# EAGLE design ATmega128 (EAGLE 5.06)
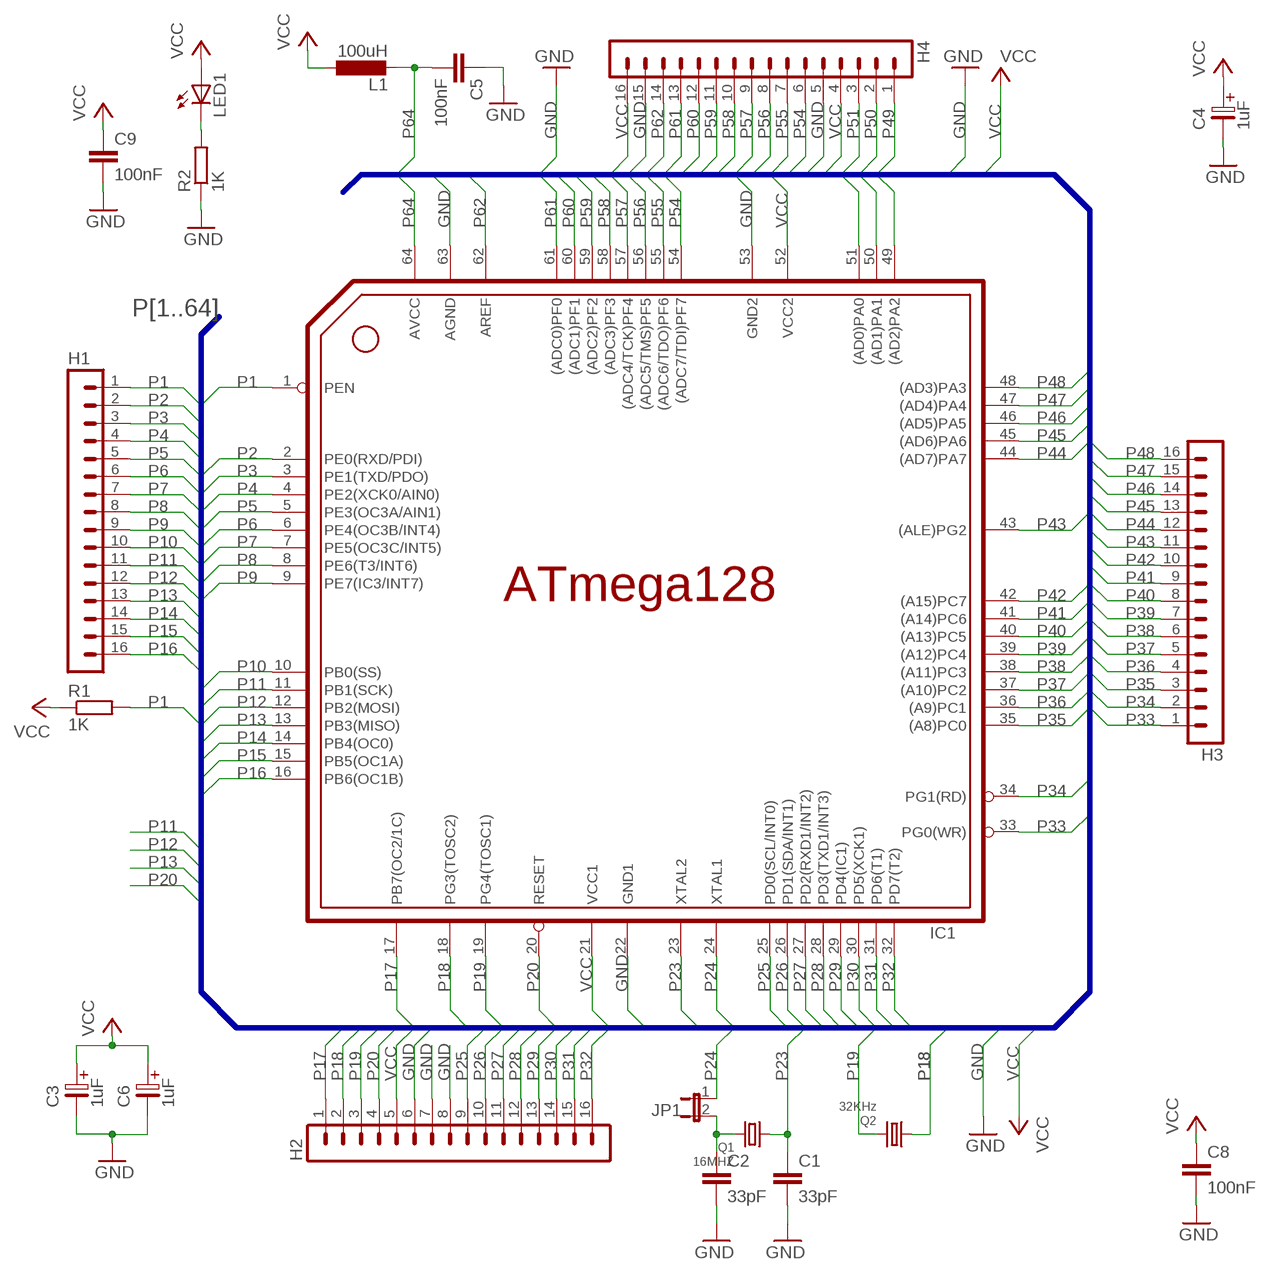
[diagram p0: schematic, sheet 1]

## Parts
C1  33pF  CAP2.5  [CAP2.5]
C2  33pF  CAP2.5  [CAP2.5]
C3  1uF  ELC2.5  [ELC2.5]
C4  1uF  ELC2.5  [ELC2.5]
C5  100nF  CAP2.5  [CAP2.5]
C6  1uF  ELC2.5  [ELC2.5]
C8  100nF  CAP2.5  [CAP2.5]
C9  100nF  CAP2.5  [CAP2.5]
H1  HEADER-16PIN  [HEADER-16PIN]
H2  HEADER-16PIN  [HEADER-16PIN]
H3  HEADER-16PIN  [HEADER-16PIN]
H4  HEADER-16PIN  [HEADER-16PIN]
IC1  ATMEGA128TQFP  [HEADER64PIN_MCU]
JP1  JP1E  [JP1]
L1  100uH  L-EU0204/7  [0204/7]
LED1  LED3MM  [LED3MM]
Q1  16MHZ  CRYSTALHC  [HC49]
Q2  32KHz  CRYSTALTC  [TC26]
R1  1K  R-5-7M  [R-7]
R2  1K  R-5-7M  [R-7]

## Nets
GND: C1.2 C2.2 C3.2 C4.2 C5.1 C6.2 C8.2 C9.2 H2.6 H2.7 H2.8 H4.5 H4.15 IC1.22(GND1) IC1.53(GND2) IC1.63(AGND) R2.1
N$1: LED1.K(C) R2.2
N$66: C2.1 JP1.2 Q1.2
P1: H1.1 IC1.1(PEN) R1.2
P2: H1.2 IC1.2(PE0(RXD/PDI))
P3: H1.3 IC1.3(PE1(TXD/PDO))
P4: H1.4 IC1.4(PE2(XCK0/AIN0))
P5: H1.5 IC1.5(PE3(OC3A/AIN1))
P6: H1.6 IC1.6(PE4(OC3B/INT4))
P7: H1.7 IC1.7(PE5(OC3C/INT5))
P8: H1.8 IC1.8(PE6(T3/INT6))
P9: H1.9 IC1.9(PE7(IC3/INT7))
P10: H1.10 IC1.10(PB0(SS))
P11: H1.11 IC1.11(PB1(SCK))
P12: H1.12 IC1.12(PB2(MOSI))
P13: H1.13 IC1.13(PB3(MISO))
P14: H1.14 IC1.14(PB4(OC0))
P15: H1.15 IC1.15(PB5(OC1A))
P16: H1.16 IC1.16(PB6(OC1B))
P17: H2.1 IC1.17(PB7(OC2/1C))
P18: H2.2 IC1.18(PG3(TOSC2)) Q2.1
P19: H2.3 IC1.19(PG4(TOSC1)) Q2.2
P20: H2.4 IC1.20(RESET)
P23: C1.1 IC1.23(XTAL2) Q1.1
P24: IC1.24(XTAL1) JP1.1
P25: H2.9 IC1.25(PD0(SCL/INT0))
P26: H2.10 IC1.26(PD1(SDA/INT1))
P27: H2.11 IC1.27(PD2(RXD1/INT2))
P28: H2.12 IC1.28(PD3(TXD1/INT3))
P29: H2.13 IC1.29(PD4(IC1))
P30: H2.14 IC1.30(PD5(XCK1))
P31: H2.15 IC1.31(PD6(T1))
P32: H2.16 IC1.32(PD7(T2))
P33: H3.1 IC1.33(PG0(WR))
P34: H3.2 IC1.34(PG1(RD))
P35: H3.3 IC1.35((A8)PC0)
P36: H3.4 IC1.36((A9)PC1)
P37: H3.5 IC1.37((A10)PC2)
P38: H3.6 IC1.38((A11)PC3)
P39: H3.7 IC1.39((A12)PC4)
P40: H3.8 IC1.40((A13)PC5)
P41: H3.9 IC1.41((A14)PC6)
P42: H3.10 IC1.42((A15)PC7)
P43: H3.11 IC1.43((ALE)PG2)
P44: H3.12 IC1.44((AD7)PA7)
P45: H3.13 IC1.45((AD6)PA6)
P46: H3.14 IC1.46((AD5)PA5)
P47: H3.15 IC1.47((AD4)PA4)
P48: H3.16 IC1.48((AD3)PA3)
P49: H4.1 IC1.49((AD2)PA2)
P50: H4.2 IC1.50((AD1)PA1)
P51: H4.3 IC1.51((AD0)PA0)
P54: H4.6 IC1.54((ADC7/TDI)PF7)
P55: H4.7 IC1.55((ADC6/TDO)PF6)
P56: H4.8 IC1.56((ADC5/TMS)PF5)
P57: H4.9 IC1.57((ADC4/TCK)PF4)
P58: H4.10 IC1.58((ADC3)PF3)
P59: H4.11 IC1.59((ADC2)PF2)
P60: H4.12 IC1.60((ADC1)PF1)
P61: H4.13 IC1.61((ADC0)PF0)
P62: H4.14 IC1.62(AREF)
P64: C5.2 IC1.64(AVCC) L1.2
VCC: C3.1 C4.1 C6.1 C8.1 C9.1 H2.5 H4.4 H4.16 IC1.21(VCC1) IC1.52(VCC2) L1.1 LED1.A R1.1

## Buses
P[1..64]

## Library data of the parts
C1 C2 C5 C8 C9 = WALID2008A:CAP: Ceramic Capacitor
C3 C4 C6 = WALID2008A:ELC: Electric Capacitor
H1-H4 = WALID2008A:HEADER-16PIN: Header 16 Pin
IC1 = WALID2008A:ATMEGA128: MICROCONTROLLER 128 Kbytes FLASH 4 Kbytes SRAM 4 Kbytes EEPROM DUAL USART 8-channel 10 bit ADC
JP1 = jumper:JP1E: JUMPER
L1 = WALID2008A:L-EU: INDUCTOR, European symbol
LED1 = led:LED: LED
Q1 Q2 = WALID2008A:CRYSTAL: Crystal
R1 R2 = WALID2008A:R-5: Resistor 5, 7,8, 10, 12, 13, 15, 17, 19, 20, 25, 28, 30mm

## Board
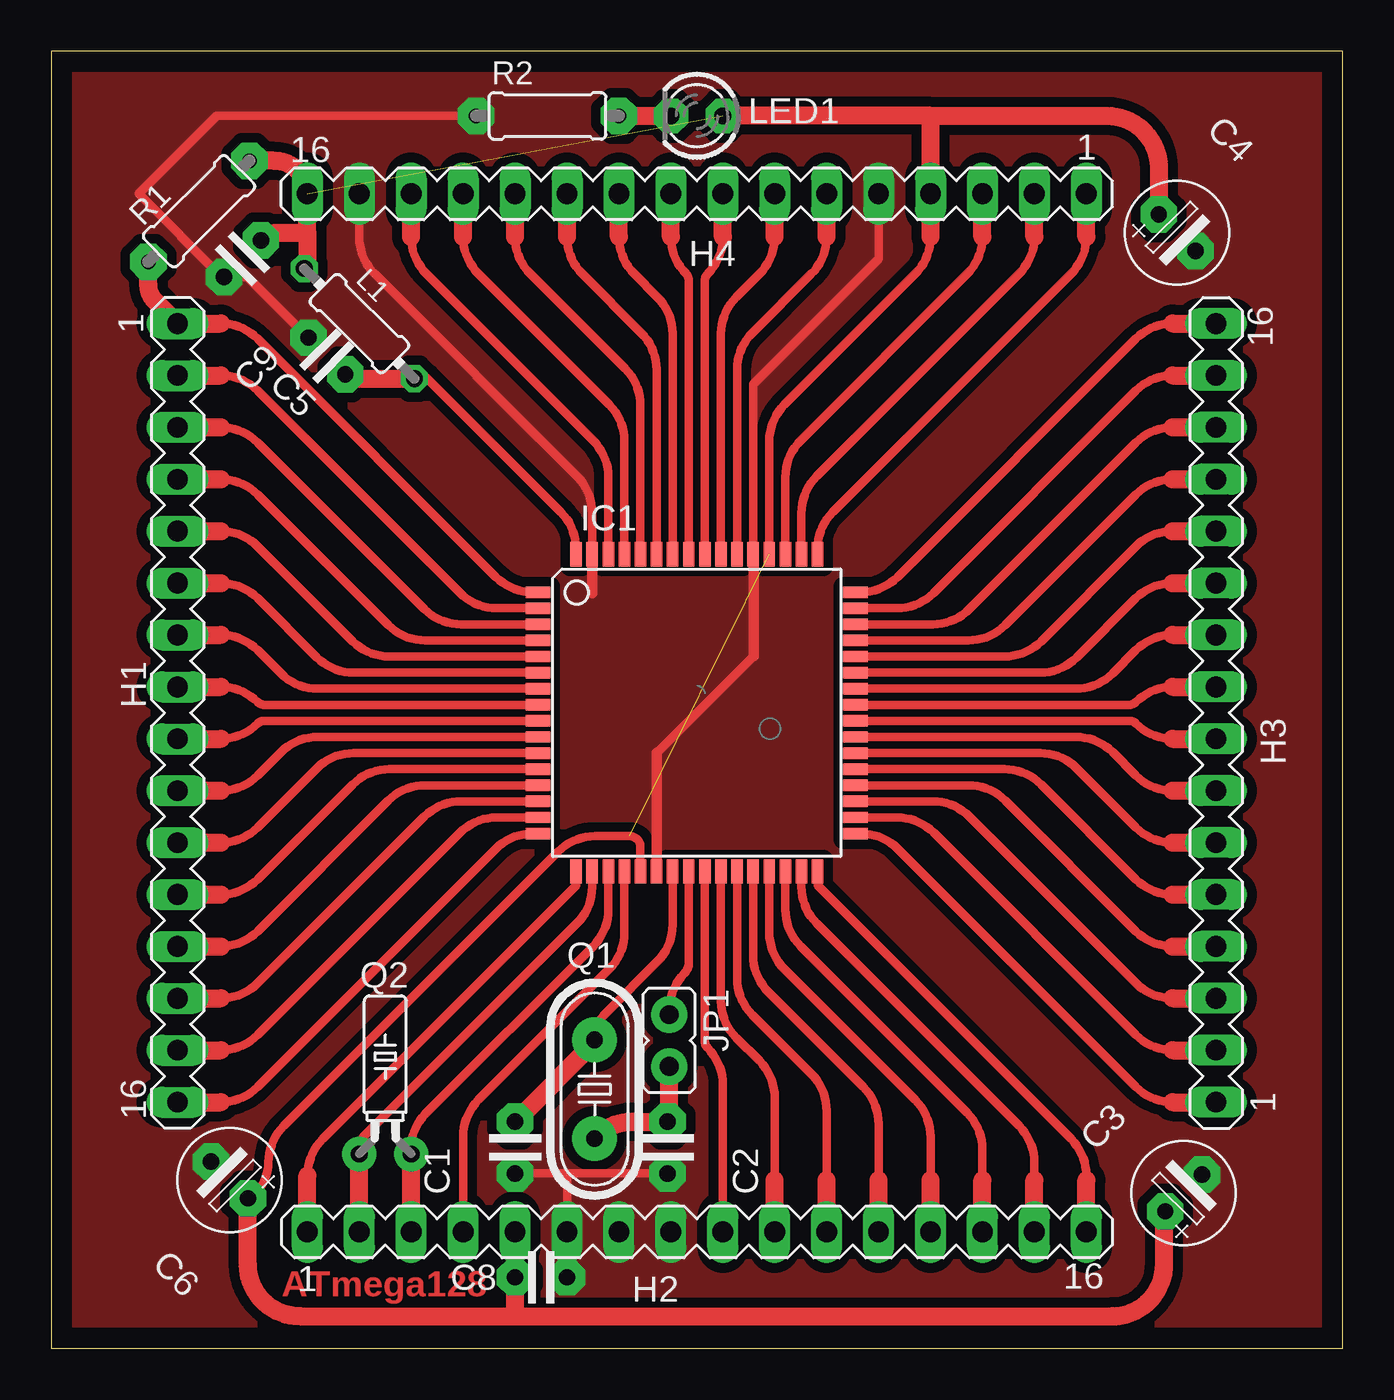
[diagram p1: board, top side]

Size 63.17 x 63.48 mm. Coordinates in mm from the lower left corner, seen from the top.
Outline: 0,63.48 0,0 63.17,0 63.17,63.48 0,63.48
Copper layers (1*16): Top 0.035mm / dielectric 1.5mm / Bottom 0.035mm
Design rules "default *": minimum track width 20mil, minimum drill 24mil, track to track 8mil, track to pad 8mil, pad to pad 8mil, via to via 8mil, smd to smd 8mil, copper to edge 40mil, drill to drill 8mil, minimum pad ring 10mil, minimum via ring 8mil, stop-mask expansion 4mil, vias tented up to drill 0mil, thermal gap 10mil

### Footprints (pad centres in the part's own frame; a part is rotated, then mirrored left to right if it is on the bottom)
CAP2.5 = drill 0.8 pad 1.778 octagon: 1 -1.27,0; 2 1.27,0
ELC2.5 = drill 0.8 pad 1.778 octagon: 1 -1.27,0; 2 1.27,0
HEADER-16PIN = drill 1.016 long: 1 -17.78,0; 2 -15.24,0; 3 -12.7,0; 4 -10.16,0; 5 -7.62,0; 6 -5.08,0; 7 -2.54,0; 8 0,0; 9 2.54,0; 10 5.08,0; 11 7.62,0; 12 10.16,0; 13 12.7,0; 14 15.24,0; 15 17.78,0; 16 20.32,0
HEADER64PIN_MCU = smd 1.194 x 0.559: 1 -7.76,5.905; 2 -7.76,5.118; 3 -7.76,4.331; 4 -7.76,3.543; 5 -7.76,2.756; 6 -7.76,1.968; 7 -7.76,1.181; 8 -7.76,0.394; 9 -7.76,-0.394; 10 -7.76,-1.181; 11 -7.76,-1.968; 12 -7.76,-2.756; 13 -7.76,-3.543; 14 -7.76,-4.331; 15 -7.76,-5.118; 16 -7.76,-5.905; 33 7.76,-5.905; 34 7.76,-5.118; 35 7.76,-4.331; 36 7.76,-3.543; 37 7.76,-2.756; 38 7.76,-1.968; 39 7.76,-1.181; 40 7.76,-0.394; 41 7.76,0.394; 42 7.76,1.181; 43 7.76,1.968; 44 7.76,2.756; 45 7.76,3.543; 46 7.76,4.331; 47 7.76,5.118; 48 7.76,5.905 | smd 0.559 x 1.194: 17 -5.905,-7.76; 18 -5.118,-7.76; 19 -4.331,-7.76; 20 -3.543,-7.76; 21 -2.756,-7.76; 22 -1.968,-7.76; 23 -1.181,-7.76; 24 -0.394,-7.76; 25 0.394,-7.76; 26 1.181,-7.76; 27 1.968,-7.76; 28 2.756,-7.76; 29 3.543,-7.76; 30 4.331,-7.76; 31 5.118,-7.76; 32 5.905,-7.76; 49 5.905,7.76; 50 5.118,7.76; 51 4.331,7.76; 52 3.543,7.76; 53 2.756,7.76; 54 1.968,7.76; 55 1.181,7.76; 56 0.394,7.76; 57 -0.394,7.76; 58 -1.181,7.76; 59 -1.968,7.76; 60 -2.756,7.76; 61 -3.543,7.76; 62 -4.331,7.76; 63 -5.118,7.76; 64 -5.905,7.76
JP1 = drill 0.914 pad 1.778 round: 1 0,-1.27; 2 0,1.27
0204/7 = drill 0.813 octagon: 1 -3.81,0; 2 3.81,0
LED3MM = drill 0.813 pad 1.676 octagon: A -1.27,0; K 1.27,0
HC49 = drill 0.813 pad 2.184 round: 1 -2.413,0; 2 2.413,0
TC26 = drill 0.813 pad 1.676 round: 1 -1.27,-5.08; 2 1.27,-5.08
R-7 = drill 0.7 pad 1.778 octagon: 1 -3.175,0; 2 3.81,0

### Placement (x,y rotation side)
C1  22.69,9.83 270 top
C2  30.16,9.83 270 top
C3  55.4,7.6 45 top
C4  55.08,54.59 315 top
C5  13.49,48.56 315 top
C6  8.72,8.24 135 top
C8  23.97,3.48 0 top
C9  9.36,53.33 225 top
H1  6.19,32.37 270 top
H2  30.31,5.7 0 top
H3  56.98,29.83 90 top
H4  32.86,56.5 180 top
IC1  31.58,31.1 0 top
JP1  30.24,15.07 180 top
L1  15.08,50.15 315 top
LED1  31.58,60.31 180 top
Q1  26.58,12.69 270 top
Q2  16.34,14.59 0 top
R1  7.45,55.86 225 top
R2  23.97,60.31 0 top

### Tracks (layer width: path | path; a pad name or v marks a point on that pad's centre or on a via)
GND
  Top 0.406: H4.5 40.47,53.33 34.34,47.19 IC1.53 34.34,38.74 34.36,38.72 | C1.2 25.23,8.56 | 25.23,8.56 C2.2 30.31,8.56 | 25.23,8.56 H2.6 | 29.62,29.13 34.36,33.88 | C5.1 9.62,52.43 C9.2 8.35,52.43 4.28,56.5 8.09,60.31 R2.1 | IC1.63 26.47,38.98 26.47,40.88 arc45 25.72,42.68 15.82,52.58 arc-45 15.08,54.38 H4.15
  Top 0.508: IC1.22 29.62,29.13 | 34.36,33.88 34.36,38.72 | 26.47,36.95 26.47,38.98
  pour Top (isolate 0.483, no thermals): -0.8,66.34 68.41,66.34 68.41,-0.97 -0.8,-0.97
N$1
  Top 0.889: R2.2 LED1.K
N$66
  Top 0.406: JP1.2 30.19,13.75 30.24,13.7 | C2.1 30.24,11.1
  Top 0.889: 30.24,11.1 30.24,13.7 | Q1.2 26.58,10.3 26.63,10.35 arc-45 28.43,11.1 C2.1
P1
  Top 0.406: 8.31,50.15 arc-45 10.1,49.41 21.76,37.75 arc45 23.56,37.01 IC1.1 | R1.2
  Top 0.889: 8.31,50.15 H1.1 5.08,51.25 arc-45 4.76,52.04 R1.2
P2
  Top 0.406: 8.31,47.61 arc-45 10.1,46.87 20.01,36.96 arc45 21.8,36.22 IC1.2
  Top 0.889: H1.2 8.31,47.61
P3
  Top 0.406: 8.31,45.07 arc-45 10.1,44.33 18.25,36.17 arc45 20.05,35.43 IC1.3
  Top 0.889: H1.3 8.31,45.07
P4
  Top 0.406: 8.31,42.53 arc-45 10.1,41.79 16.5,35.39 arc45 18.3,34.64 IC1.4
  Top 0.889: H1.4 8.31,42.53
P5
  Top 0.406: 8.31,39.99 arc-45 10.1,39.25 14.75,34.6 arc45 16.55,33.86 IC1.5
  Top 0.889: H1.5 8.31,39.99
P6
  Top 0.406: 8.31,37.45 arc-45 10.1,36.71 13,33.81 arc45 14.79,33.07 IC1.6
  Top 0.889: H1.6 8.31,37.45
P7
  Top 0.406: 8.31,34.91 arc-45 10.1,34.17 11.25,33.02 arc45 13.04,32.28 IC1.7
  Top 0.889: H1.7 8.31,34.91
P8
  Top 0.406: 8.31,32.37 arc-45 10.1,31.63 arc45 10.42,31.49 IC1.8
  Top 0.889: H1.8 8.31,32.37
P9
  Top 0.406: 8.31,29.83 arc45 10.1,30.57 arc-45 10.42,30.71 IC1.9
  Top 0.889: H1.9 8.31,29.83
P10
  Top 0.406: 8.31,27.29 arc45 10.1,28.03 11.25,29.17 arc-45 13.04,29.92 IC1.10
  Top 0.889: H1.10 8.31,27.29
P11
  Top 0.406: 8.31,24.75 arc45 10.1,25.49 13,28.39 arc-45 14.79,29.13 IC1.11
  Top 0.889: H1.11 8.31,24.75
P12
  Top 0.406: 8.31,22.21 arc45 10.1,22.95 14.75,27.6 arc-45 16.55,28.34 IC1.12
  Top 0.889: H1.12 8.31,22.21
P13
  Top 0.406: 8.31,19.67 arc45 10.1,20.41 16.5,26.81 arc-45 18.3,27.56 IC1.13
  Top 0.889: H1.13 8.31,19.67
P14
  Top 0.406: 8.31,17.13 arc45 10.1,17.87 18.25,26.02 arc-45 20.05,26.77 IC1.14
  Top 0.889: H1.14 8.31,17.13
P15
  Top 0.406: 8.31,14.59 arc45 10.1,15.33 20.01,25.24 arc-45 21.8,25.98 IC1.15
  Top 0.889: H1.15 8.31,14.59
P16
  Top 0.406: 8.31,12.05 arc45 10.1,12.79 21.76,24.45 arc-45 23.56,25.2 IC1.16
  Top 0.889: H1.16 8.31,12.05
P17
  Top 0.406: IC1.17 25.68,22.66 13.28,10.25 arc45 12.53,8.46
  Top 0.889: H2.1 12.53,8.46
P18
  Top 0.406: IC1.18 26.47,22.59 arc-45 25.72,20.79 15.3,10.37 arc45 15.08,9.83
  Top 0.889: H2.2 Q2.1
  Top 1.016: Q2.1 15.08,9.83
P19
  Top 0.406: 17.61,9.83 arc-45 18.29,11.45 26.51,19.67 arc45 27.25,21.47 IC1.19
  Top 0.889: H2.3 Q2.2
  Top 1.016: Q2.2 17.61,9.83
P20
  Top 0.406: H2.4 20.16,10.36 arc-45 20.9,12.16 27.3,18.56 arc45 28.04,20.35 IC1.20
P23
  Top 0.406: Q1.1 26.58,15.07 | Q1.1 | IC1.23 30.4,20.73 arc-45 29.66,18.94 27.12,16.4 arc45 Q1.1 | 26.58,14.99 Q1.1
  Top 0.889: C1.1 26.58,14.99
P24
  Top 0.406: JP1.1 30.24,16.55 arc-45 30.98,18.35 arc45 31.19,18.86 IC1.24
P25
  Top 0.406: H2.9 32.86,12.9 arc45 32.11,14.7 arc-45 31.98,15.02 IC1.25
P26
  Top 0.406: 35.39,8.24 35.39,12.27 arc45 34.65,14.06 33.51,15.21 arc-45 32.77,17 IC1.26
  Top 0.889: H2.10 35.39,8.24
P27
  Top 0.406: 37.94,8.24 37.94,11.63 arc45 37.19,13.43 34.3,16.32 arc-45 33.55,18.12 IC1.27
  Top 0.889: H2.11 37.94,8.24
P28
  Top 0.406: 40.47,8.24 40.47,11 arc45 39.73,12.79 35.08,17.44 arc-45 34.34,19.24 IC1.28
  Top 0.889: H2.12 40.47,8.24
P29
  Top 0.406: 43.02,8.24 43.02,10.36 arc45 42.27,12.16 35.87,18.56 arc-45 35.13,20.35 IC1.29
  Top 0.889: H2.13 43.02,8.24
P30
  Top 0.406: 45.55,8.24 45.55,9.73 arc45 44.81,11.52 36.66,19.67 arc-45 35.92,21.47 IC1.30
  Top 0.889: H2.14 45.55,8.24
P31
  Top 0.406: 48.09,8.24 48.09,9.09 arc45 47.35,10.89 37.45,20.79 arc-45 36.7,22.59 IC1.31
  Top 0.889: H2.15 48.09,8.24
P32
  Top 0.406: IC1.32 37.49,22.66 49.89,10.25 arc-45 50.63,8.46 50.63,8.24
  Top 0.889: H2.16 50.63,8.24
P33
  Top 0.406: IC1.33 39.61,25.2 arc-45 41.41,24.45 53.07,12.79 arc45 54.86,12.05
  Top 0.889: 54.86,12.05 H3.1
P34
  Top 0.406: IC1.34 41.37,25.98 arc-45 43.16,25.24 53.07,15.33 arc45 54.86,14.59
  Top 0.889: 54.86,14.59 H3.2
P35
  Top 0.406: IC1.35 43.12,26.77 arc-45 44.91,26.02 53.07,17.87 arc45 54.86,17.13
  Top 0.889: 54.86,17.13 H3.3
P36
  Top 0.406: IC1.36 44.87,27.56 arc-45 46.67,26.81 53.07,20.41 arc45 54.86,19.67
  Top 0.889: 54.86,19.67 H3.4
P37
  Top 0.406: IC1.37 46.62,28.34 arc-45 48.42,27.6 53.07,22.95 arc45 54.86,22.21
  Top 0.889: 54.86,22.21 H3.5
P38
  Top 0.406: IC1.38 48.38,29.13 arc-45 50.17,28.39 53.07,25.49 arc45 54.86,24.75
  Top 0.889: 54.86,24.75 H3.6
P39
  Top 0.406: IC1.39 50.13,29.92 arc-45 51.92,29.17 53.07,28.03 arc45 54.86,27.29
  Top 0.889: 54.86,27.29 H3.7
P40
  Top 0.406: IC1.40 52.75,30.71 arc-45 53.07,30.57 arc45 54.86,29.83
  Top 0.889: 54.86,29.83 H3.8
P41
  Top 0.406: IC1.41 52.75,31.49 arc45 53.07,31.63 arc-45 54.86,32.37
  Top 0.889: 54.86,32.37 H3.9
P42
  Top 0.406: IC1.42 50.13,32.28 arc45 51.92,33.02 53.07,34.17 arc-45 54.86,34.91
  Top 0.889: 54.86,34.91 H3.10
P43
  Top 0.406: IC1.43 48.38,33.07 arc45 50.17,33.81 53.07,36.71 arc-45 54.86,37.45
  Top 0.889: 54.86,37.45 H3.11
P44
  Top 0.406: IC1.44 46.62,33.86 arc45 48.42,34.6 53.07,39.25 arc-45 54.86,39.99
  Top 0.889: 54.86,39.99 H3.12
P45
  Top 0.406: IC1.45 44.87,34.64 arc45 46.67,35.39 53.07,41.79 arc-45 54.86,42.53
  Top 0.889: 54.86,42.53 H3.13
P46
  Top 0.406: IC1.46 43.12,35.43 arc45 44.91,36.17 53.07,44.33 arc-45 54.86,45.07
  Top 0.889: 54.86,45.07 H3.14
P47
  Top 0.406: IC1.47 41.37,36.22 arc45 43.16,36.96 53.07,46.87 arc-45 54.86,47.61
  Top 0.889: 54.86,47.61 H3.15
P48
  Top 0.406: IC1.48 39.61,37.01 arc45 41.41,37.75 53.07,49.41 arc-45 54.86,50.15
  Top 0.889: 54.86,50.15 H3.16
P49
  Top 0.406: IC1.49 37.49,39.13 arc-45 38.23,40.92 49.89,52.58 arc45 50.63,54.38
  Top 0.889: 50.63,54.38 H4.1
P50
  Top 0.406: IC1.50 36.7,40.88 arc-45 37.45,42.68 47.35,52.58 arc45 48.09,54.38
  Top 0.889: 48.09,54.38 H4.2
P51
  Top 0.406: IC1.51 35.92,42.63 arc-45 36.66,44.43 44.81,52.58 arc45 45.55,54.38
  Top 0.889: 45.55,54.38 H4.3
P54
  Top 0.406: IC1.54 33.55,47.89 arc-45 34.3,49.69 37.19,52.58 arc45 37.94,54.38
  Top 0.889: 37.94,54.38 H4.6
P55
  Top 0.406: IC1.55 32.77,49.64 arc-45 33.51,51.44 34.65,52.58 arc45 35.39,54.38
  Top 0.889: 35.39,54.38 H4.7
P56
  Top 0.406: IC1.56 31.98,52.26 arc-45 32.11,52.58 arc45 32.86,54.38
  Top 0.889: 32.86,54.38 H4.8
P57
  Top 0.406: IC1.57 31.19,52.26 arc45 31.06,52.58 arc-45 30.31,54.38
  Top 0.889: 30.31,54.38 H4.9
P58
  Top 0.406: IC1.58 30.4,49.64 arc45 29.66,51.44 28.52,52.58 arc-45 27.77,54.38
  Top 0.889: 27.77,54.38 H4.10
P59
  Top 0.406: IC1.59 29.62,47.89 arc45 28.87,49.69 25.98,52.58 arc-45 25.23,54.38
  Top 0.889: 25.23,54.38 H4.11
P60
  Top 0.406: IC1.60 28.83,46.14 arc45 28.08,47.93 23.44,52.58 arc-45 22.69,54.38
  Top 0.889: 22.69,54.38 H4.12
P61
  Top 0.406: IC1.61 28.04,44.39 arc45 27.3,46.18 20.9,52.58 arc-45 20.16,54.38
  Top 0.889: 20.16,54.38 H4.13
P62
  Top 0.406: IC1.62 27.25,42.63 arc45 26.51,44.43 18.36,52.58 arc-45 17.61,54.38
  Top 0.889: 17.61,54.38 H4.14
P64
  Top 0.406: L1.2 17.86,47.53 18.33,47.53 24.94,40.92 arc-45 25.68,39.13 IC1.64 | 14.59,47.46 C5.2
  Top 0.889: C5.2 | 14.59,47.46 L1.2
VCC  (2 unrouted)
  Top 0.406: IC1.52 35.13,44.39 arc-45 35.87,46.18 42.27,52.58 arc45 43.02,54.38 | IC1.21 28.83,24.54 arc90 28.3,25.07 26.61,25.07 arc45 24.81,24.32 11.37,10.89 arc45 10.63,9.09 arc-45 10.03,7.64 9.68,7.29 C6.1 | C6.1 | 54.44,6.71 C3.1
  Top 0.889: 43.02,54.38 H4.4 43.02,60.31 | 22.69,1.57 C8.1 | C8.1 H2.5 C8.1 | C6.1 9.62,4.11 arc90 12.16,1.57 22.69,1.57 | 43.02,60.31 51.64,60.31 arc-90 54.18,57.77 C4.1 | 43.02,60.31 LED1.A | 22.69,1.57 51.91,1.57 arc90 54.44,4.11 54.44,6.71 | L1.1 arc45 12.53,53.22 12.53,54.59 | 12.53,54.59 H4.16 arc90 10.92,58.11 R1.1 | C9.1 arc-45 11.16,54.59 12.53,54.59

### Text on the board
Top: ATmega128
